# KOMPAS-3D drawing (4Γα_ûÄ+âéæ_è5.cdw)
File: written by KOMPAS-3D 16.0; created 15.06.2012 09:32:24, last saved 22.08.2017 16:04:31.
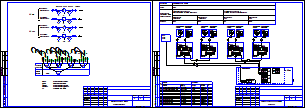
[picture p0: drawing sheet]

Sheets 1-2: A3, landscape

Title block, sheet 1: name: г. Москва, ул. Нежинская, д. 14, к.8 (кв. 1 и кв. 2); sheet number: 1; sheets: 27 / 28; sheet format: A3; stored path: D:\Проекты\Лыткарино\ул. Квартал 3А, д.25\710.74 РП.cdw; cell 320: Р
Title block, sheet 2: sheet number: 2

Views: Вид 2, Вид 3, Вид 4, Вид 5
Referenced files in C:\Program Files (x86)\ASCON\KOMPAS-3D V16\Sys\: SPDS.lcs, EngSys.lcs, GRAPHIC.LHS
Referenced files: graphic.tdp
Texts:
  МО, Клинский район, д. Решетниково, ул. Центральная, д.14
  GOST Common
  Normal
  List Paragraph
  heading 3
  для схемы
  txt
  краны
  Фоновая заливка
  Т0-элементы
  ВРУ
  Плата подключений
  СБ МКТС
  каб.
  Начало
  трассы
  Трассы
  Марка
  Проложен
  Датчик температуры (Т1)
  Датчик температуры (Т2)
  Датчик температуры (Т3)
  Датчик температуры (Т4)
  Датчик давления (Т2)
  Датчик давления (Т1)
  Датчик давления (Т3)
  Датчик давления (Т4)
  Изм. модуль (Т2)
  Изм. модуль (Т1)
  Изм. модуль (Т3)
  Изм. модуль (Т4)
  ВРУ 220В, 50 Гц
  ИМ1 УУТЭ
  ИМ2 УУТЭ
  ИМ1 УУГВС
  ИМ2 УУГВС
  ИМ (Т1)
  ИМ (Т3)
  FTP
  ПВС
  Конец
  Кол-во и
  сеч. жил
  Длина,
  Pt 100
  Преобразователь
  температуры
  давления
  UP+
  UP-
  ИМП
  Лин
  Измерительный
  модуль М121
  Агрегат
  Системный блок  МКТС
  Среда
  Вода
  параметра и место
  отбора импульса
  Учет тепловой энергии и
  теплоносителя системы отопления
  Подающий
  трубопровод
  отопления
  Обратный
  расхода горячей водысистемы ГВС
  ГВС
  ИМ1
  ИМ2
  ИМ3
  ИМ4
  Преобразователь расхода
  Термопреобразователь
  Преобразователь давления
  Преобразователь цифровой
  Системный блок МКТС
  приборы
  по месту
  шкаф
  учета
  UQIES
  УУГВС
  УУТЭ
  Функциональная схема
  Размеры, параметризация
  сит. план
  подача ГВС
  обратка ГВС
  хвс
  обратка
  POLYLINE_STYLE_0.25_RGB_0_0_0
  стены
  Основная (не является границей для штриховки)
  POLYLINE_STYLE_0.18_RGB_0_0_0
  ХВС
  зеленая
  Красная тонкая
  арматура
  Подача
  Скрытая линия
  Ось Z
  Ось Y
  Ось X
  Образующая трубопровода (проектируемого)
  Трубопровод толщиной 0.6мм (одна линия)
  Трубопровод толщиной 1.2мм (одна линия)
  Трубопровод толщиной 1.0мм (одна линия)
  Трубопровод толщиной 0.8мм (одна линия)
  Трубопровод существующий (одна линия)
  Трубопровод невидимый (одна линия)
  Трубопровод демонтируемый (одна линия)
  Осевая трубопровода
  Осевая трубопровода (демонтируемого)
  Образующая трубопровода (существующего)
  Образующая трубопровода (невидимого)
  Изолированный трубопровод проектируемый (одна линия)
  Изолированный трубопровод существующий (одна линия)
  Образующая изоляции
  Изоляция
  Изолированный трубопровод невидимый (одна линия)
  Штрих пвс 075
  штрих пвс 2,5
  существующее оборудование
  Существующее оборудование
  K5LT_BASIC_RGB_0_0_255_THICK_0.53
  POLYLINE_STYLE_1.51_RGB_0_0_255
  POLYLINE_STYLE_0.50_RGB_128_128_128
  K5LT_AXLED_RGB_255_128_0_SC_1_THICK_0.18
  ACAD_ISO04W100_RGB_0_0_0_SC_1_THICK_0.18
  тонкая черная
  пломбировка
  Провода
  синий штрих
  Стили документа
  G2co
  расход вторичной воды объемный
  расход вторичной воды объемный при 70гр
  Gco
  расход теплоносителя массовый
  расход теплоносит объемн подающ
  расход теплоносит объемн обр
  Лапир
  Ghvs
  Im1
  Im2
  Im3
  Im4
  Im5
  Khvs
  норматив ХВС
  число подъездов
  число этажей
  Nkv
  число квартир
  тепловая нагрузка на отопление
  сумма Q
  Qgvs
  тепловая нагрузка ГВС
  тепловая нагрузка на циркуляцию ГВС
  иммитовставка или под манометр
  ro1
  ro2
  ro3
  ro4
  верх предел темп граф
  нижн предел темп граф
  темп подачи ГВС
  темп обр ГВС
  темр хол воды
  vzdh
  Kchn
  Ktp
  Knp
  beta
  tnv
  Vклап
  KLP
  RPD
  RDS
  PUMP
  ro5
  Переход К-76 x 3-38 x 2-09Г2С ГОСТ 17378-2001
  Переход ГОСТ 17378-2001
  Переход
  ГОСТ
  Сталь 09Г2С ГОСТ 19281-89
  Переход К-76 x 3-45 x 2,5-09Г2С ГОСТ 17378-2001
  Переход К-57 x 3-38 x 2-09Г2С ГОСТ 17378-2001
  Переход К-57 x 3-32 x 2-09Г2С ГОСТ 17378-2001
  Втулка 20x50
  Переход К-108 x 4-57 x 3-09Г2С ГОСТ 17378-2001
  Переход К-45 x 2,5-32 x 2-09Г2С ГОСТ 17378-2001
  Переход К-89 x 3,5-45 x 2,5-09Г2С ГОСТ 17378-2001
  Переход К-133 x 5-108 x 4-09Г2С ГОСТ 17378-2001
  Переход К-159 x 4,5-89 x 3,5-09Г2С ГОСТ 17378-2001
  Переход К-45 x 2,5-38 x 2-09Г2С ГОСТ 17378-2001
  Фланец 1-32-1 Ст3сп ГОСТ 12820-80
  Фланцы
  Фланец
  квадратный
  Ст3сп
  Ст3сп ГОСТ 380-2005
  Переход К-57 x 3-45 x 2,5-09Г2С ГОСТ 17378-2001
  Переход К-76 x 3-57 x 3-09Г2С ГОСТ 17378-2001
  Фланец 1-50-16 Ст3сп ГОСТ 12821-80
  Переход К-89 x 3,5-76 x 3,5-09Г2С ГОСТ 17378-2001
  Переход К-108 x 4-89 x 3,5-09Г2С ГОСТ 17378-2001
  Тройник 159 x 4,5-09Г2С ГОСТ 17376-2001
  Тройники ГОСТ 17376-2001
  Тройник
  Отвод 90-159 x 4-09Г2С ГОСТ 17375-2001
  Отвод ГОСТ 17375-2001
  Отвод
  Переход К-108 x 4-76 x 3,5-09Г2С ГОСТ 17378-2001
  Переход К-159 x 4,5-108 x 4-09Г2С ГОСТ 17378-2001
  Переход К-133 x 5-76 x 3,5-09Г2С ГОСТ 17378-2001
  Переход К-133 x 4-89 x 3,5-09Г2С ГОСТ 17378-2001
  Переход К-1-42,4 x 2,6-21,3 x 2-TS10 ГОСТ 17378-2001
  TS10
  Сталь TS10 ИСО 2604/2-75
  Фланец 1-20-16 Ст3сп ГОСТ 12820-80
  Лит-Масса-Масштаб
  Материал-Предприятие
  Title Specification
  Body Specification ( left align )
  Body Specificaton ( centered )
  Поз.
  Кол.
  Приме-
  чание
  Таблица спецификации
  Засыпка
  Штрих3
  Штрих2
  Штрих1
  Песок
  Штр0.5пр7
  Штр0.5пр12
  Штр0.3пр10
  Штр1.4пр21.21
  Штр1пр15
  Штр2.12пр35
  Штр1.5пр25
  Штр2.82пр42.42
  Штр2пр30
  SACNCR_ISO 1
  Электрощитовая
  Пр-1
  Ок-1
  вапвыапвы
  Обозначение стандарта
  Типоразмер
  Разраб.
  Пров.
  Т.контр.
  Н.контр.
  Утв.
  автоматизации
  Рабочие чертежи основного комплекта. ГОСТ Р 21.1101-2009 Ф3
  Стадия
  Лист
  Листов
  Изм.
  Кол.уч.
  №док.
  Подп.
  Дата
  Изменение
  Номер документа
  Подпись
  Наименование объекта строительства, в состав которого входит здание, наим. микр
  Наименование здания (сооружения)
  Порядковый номер листа
  Количество листов в документе
  Наименование изображения
  Индекс предприятия, выпускающего документ
  Инв. № подл.
  Подп. и дата
  Взам. инв. №
  Инвентарный номер подлинника
  Подпись принявшего подлинник на хранение
  Инвентарный номер подлинника, взамен которого выпущен данный подлинник
  Согласовано
  Формат листа
  Согласование
  03 Рабочие чертежи основного комплекта. ГОСТ Р 21.1101-2009 Ф3
  Схема соединений внешних
  проводок
Dimensions and other numbers on the sheet: 0; 220В; 50Гц; 1; 2; 3; 6; 5; 4; 2x2x0,52; 3х0,75; 15; 25; 4-20; 17; 1,2,3,4; 5,6,7,8; 9,10,11,12; 13,14,15,16; 10; 13; 14; 9; 60; 4,0; 2,6582; 0,0160; 16; 95; 2,6160; 3,0; 0,7862; 0,0060; 70; 11; 12; 7; 8; 0,4088; 50; 09Г2С; 19; 20; 21; 22; 23; 24; 26; 30; 31; 33; 34; 52; 64; 65; 66; 67; 69; 71; 72; 73; 74; 75; 27; 28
